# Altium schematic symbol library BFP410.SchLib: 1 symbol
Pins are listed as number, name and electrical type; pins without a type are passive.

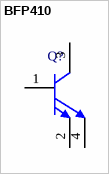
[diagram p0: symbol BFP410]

## BFP410
designator Q?
NPN Silicon RF Transistor, 4.5 V VCEO, 40 mA IC, 21.5 dB Gmax, SOT343, Green; Manufacturer: Infineon; PartNumber: BFP410; Gmax (typ): 21.5 dB; Green: yes; IC (max): 40 mA; NFmin (typ): 1.2 dB; Ptot (max): 150 mW; VCEO (max): 4.5 V
footprint INF-SOT343_V (SOT343, 4-Leads, Body 2x1.25 mm)
pins: 1 B, 2 E, 3 C, 4 E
